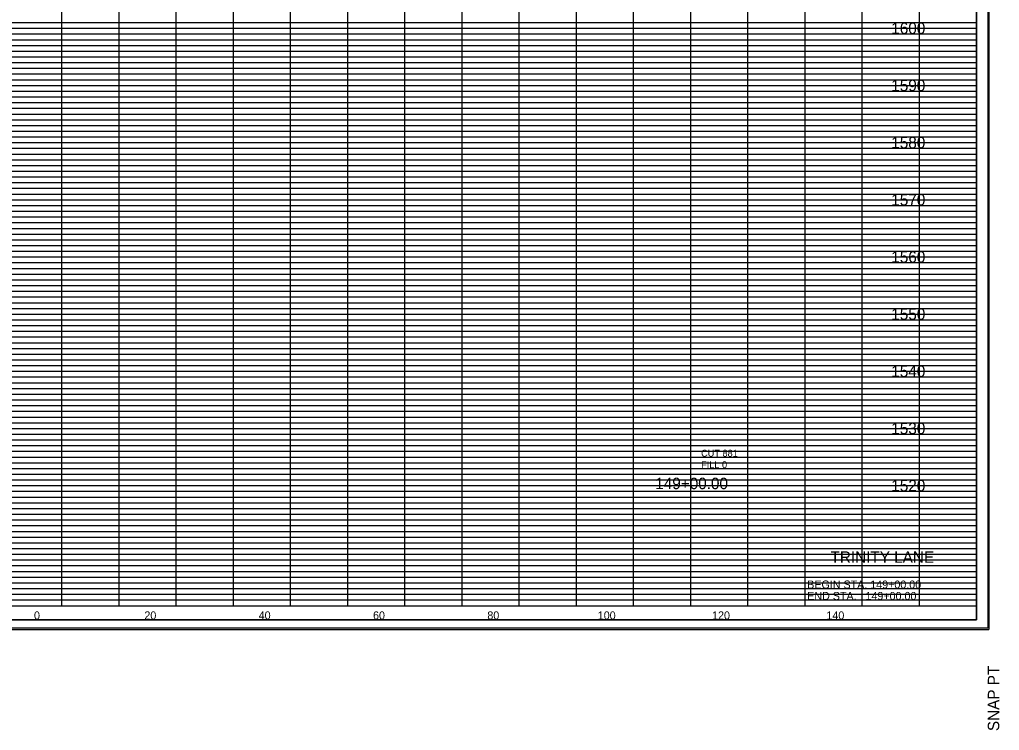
# Model space of a CAD drawing. Extents: x 980 to 1380, y 1248 to 3387.
# Drawn here: x 1152.6 to 1324, y 2868.2 to 2992.5 of the extents above; entities that cross this region are included whole.
import ezdxf

# ---------------------------------------------------------------- set-up
doc = ezdxf.new("R2010")
doc.units = 0
for name, color, linetype in [('DESIGN - SHEET - Corner Text', 7, 'Continuous'), ('DESIGN - SHEET - Light Grid', 7, 'Continuous'), ('DESIGN - SHEET - Linework', 7, 'Continuous'), ('DESIGN - SHEET - Plot Shape', 7, 'Continuous'), ('DESIGN - TYPICAL - Text', 7, 'Continuous')]:
    doc.layers.add(name, color=color, linetype=linetype)

# ---------------------------------------------------------------- blocks, each defined once
blk = doc.blocks.new('XSTSHT')
at = {"layer": 'DESIGN - SHEET - Light Grid'}
for p, q in [((8, 10.2), (16, 10.2)), ((16, 10.2), (24, 10.2)), ((24, 10.2), (32, 10.2)), ((8, 10.1), (16, 10.1)), ((16, 10.1), (24, 10.1)), ((24, 10.1), (32, 10.1)), ((8, 9.9), (16, 9.9)), ((8, 9.8), (16, 9.8)), ((16, 9.9), (24, 9.9)), ((16, 9.8), (24, 9.8)), ((24, 9.9), (32, 9.9)), ((24, 9.8), (32, 9.8)), ((8, 9.7), (16, 9.7)), ((8, 9.6), (16, 9.6)), ((16, 9.7), (24, 9.7)), ((16, 9.6), (24, 9.6)), ((24, 9.7), (32, 9.7)), ((24, 9.6), (32, 9.6)), ((8, 9.5), (16, 9.5)), ((16, 9.5), (24, 9.5)), ((24, 9.5), (32, 9.5)), ((8, 9.4), (16, 9.4)), ((8, 9.3), (16, 9.3)), ((16, 9.4), (24, 9.4)), ((16, 9.3), (24, 9.3)), ((24, 9.4), (32, 9.4)), ((24, 9.3), (32, 9.3)), ((8, 9.2), (16, 9.2)), ((8, 9.1), (16, 9.1)), ((16, 9.2), (24, 9.2)), ((16, 9.1), (24, 9.1)), ((24, 9.2), (32, 9.2)), ((24, 9.1), (32, 9.1)), ((8, 8.9), (16, 8.9)), ((8, 8.8), (16, 8.8)), ((16, 8.9), (24, 8.9)), ((16, 8.8), (24, 8.8)), ((24, 8.9), (32, 8.9)), ((24, 8.8), (32, 8.8)), ((8, 8.7), (16, 8.7)), ((8, 8.6), (16, 8.6)), ((16, 8.7), (24, 8.7)), ((16, 8.6), (24, 8.6)), ((24, 8.7), (32, 8.7)), ((24, 8.6), (32, 8.6)), ((8, 8.5), (16, 8.5)), ((8, 8.4), (16, 8.4)), ((16, 8.5), (24, 8.5)), ((16, 8.4), (24, 8.4)), ((24, 8.5), (32, 8.5)), ((24, 8.4), (32, 8.4)), ((8, 8.3), (16, 8.3)), ((16, 8.3), (24, 8.3)), ((24, 8.3), (32, 8.3)), ((8, 8.2), (16, 8.2)), ((8, 8.1), (16, 8.1)), ((16, 8.2), (24, 8.2)), ((16, 8.1), (24, 8.1)), ((24, 8.2), (32, 8.2)), ((24, 8.1), (32, 8.1)), ((8, 7.9), (16, 7.9)), ((16, 7.9), (24, 7.9)), ((24, 7.9), (32, 7.9)), ((8, 7.8), (16, 7.8)), ((16, 7.8), (24, 7.8)), ((24, 7.8), (32, 7.8)), ((8, 7.7), (16, 7.7)), ((8, 7.6), (16, 7.6)), ((16, 7.7), (24, 7.7)), ((16, 7.6), (24, 7.6)), ((24, 7.7), (32, 7.7)), ((24, 7.6), (32, 7.6)), ((8, 7.5), (16, 7.5)), ((8, 7.4), (16, 7.4)), ((16, 7.5), (24, 7.5)), ((16, 7.4), (24, 7.4)), ((24, 7.5), (32, 7.5)), ((24, 7.4), (32, 7.4)), ((8, 7.3), (16, 7.3)), ((8, 7.2), (16, 7.2)), ((16, 7.3), (24, 7.3)), ((16, 7.2), (24, 7.2)), ((24, 7.3), (32, 7.3)), ((24, 7.2), (32, 7.2)), ((8, 7.1), (16, 7.1)), ((16, 7.1), (24, 7.1)), ((24, 7.1), (32, 7.1)), ((8, 6.9), (16, 6.9)), ((16, 6.9), (24, 6.9)), ((24, 6.9), (32, 6.9)), ((8, 6.8), (16, 6.8)), ((8, 6.7), (16, 6.7)), ((16, 6.8), (24, 6.8)), ((16, 6.7), (24, 6.7)), ((24, 6.8), (32, 6.8)), ((24, 6.7), (32, 6.7)), ((8, 6.6), (16, 6.6)), ((16, 6.6), (24, 6.6)), ((24, 6.6), (32, 6.6)), ((8, 6.5), (16, 6.5)), ((8, 6.4), (16, 6.4)), ((16, 6.5), (24, 6.5)), ((16, 6.4), (24, 6.4)), ((24, 6.5), (32, 6.5)), ((24, 6.4), (32, 6.4)), ((8, 6.3), (16, 6.3)), ((8, 6.2), (16, 6.2)), ((16, 6.3), (24, 6.3)), ((16, 6.2), (24, 6.2)), ((24, 6.3), (32, 6.3)), ((24, 6.2), (32, 6.2)), ((8, 6.1), (16, 6.1)), ((16, 6.1), (24, 6.1)), ((24, 6.1), (32, 6.1)), ((8, 5.9), (16, 5.9)), ((16, 5.9), (24, 5.9)), ((24, 5.9), (32, 5.9)), ((8, 5.8), (16, 5.8)), ((8, 5.7), (16, 5.7)), ((16, 5.8), (24, 5.8)), ((16, 5.7), (24, 5.7)), ((24, 5.8), (32, 5.8)), ((24, 5.7), (32, 5.7)), ((8, 5.6), (16, 5.6)), ((8, 5.5), (16, 5.5)), ((16, 5.6), (24, 5.6)), ((16, 5.5), (24, 5.5)), ((24, 5.6), (32, 5.6)), ((24, 5.5), (32, 5.5)), ((8, 5.4), (16, 5.4)), ((16, 5.4), (24, 5.4)), ((24, 5.4), (32, 5.4)), ((8, 5.3), (16, 5.3)), ((8, 5.2), (16, 5.2)), ((16, 5.3), (24, 5.3)), ((16, 5.2), (24, 5.2)), ((24, 5.3), (32, 5.3)), ((24, 5.2), (32, 5.2)), ((8, 5.1), (16, 5.1)), ((16, 5.1), (24, 5.1)), ((24, 5.1), (32, 5.1)), ((8, 4.9), (16, 4.9)), ((8, 4.8), (16, 4.8)), ((16, 4.9), (24, 4.9)), ((16, 4.8), (24, 4.8)), ((24, 4.9), (32, 4.9)), ((24, 4.8), (32, 4.8)), ((8, 4.7), (16, 4.7)), ((16, 4.7), (24, 4.7)), ((24, 4.7), (32, 4.7)), ((8, 4.6), (16, 4.6)), ((8, 4.5), (16, 4.5)), ((16, 4.6), (24, 4.6)), ((16, 4.5), (24, 4.5)), ((24, 4.6), (32, 4.6)), ((24, 4.5), (32, 4.5)), ((8, 4.4), (16, 4.4)), ((8, 4.3), (16, 4.3)), ((16, 4.4), (24, 4.4)), ((16, 4.3), (24, 4.3)), ((24, 4.4), (32, 4.4)), ((24, 4.3), (32, 4.3)), ((8, 4.2), (16, 4.2)), ((16, 4.2), (24, 4.2)), ((24, 4.2), (32, 4.2)), ((8, 4.1), (16, 4.1)), ((16, 4.1), (24, 4.1)), ((24, 4.1), (32, 4.1)), ((8, 3.9), (16, 3.9)), ((8, 3.8), (16, 3.8)), ((16, 3.9), (24, 3.9)), ((16, 3.8), (24, 3.8)), ((24, 3.9), (32, 3.9)), ((24, 3.8), (32, 3.8)), ((8, 3.7), (16, 3.7)), ((8, 3.6), (16, 3.6)), ((16, 3.7), (24, 3.7)), ((16, 3.6), (24, 3.6)), ((24, 3.7), (32, 3.7)), ((24, 3.6), (32, 3.6)), ((8, 3.5), (16, 3.5)), ((16, 3.5), (24, 3.5)), ((24, 3.5), (32, 3.5)), ((8, 3.4), (16, 3.4)), ((8, 3.3), (16, 3.3)), ((16, 3.4), (24, 3.4)), ((16, 3.3), (24, 3.3)), ((24, 3.4), (32, 3.4)), ((24, 3.3), (32, 3.3)), ((8, 3.2), (16, 3.2)), ((8, 3.1), (16, 3.1)), ((16, 3.2), (24, 3.2)), ((16, 3.1), (24, 3.1)), ((24, 3.2), (32, 3.2)), ((24, 3.1), (32, 3.1)), ((8, 2.9), (16, 2.9)), ((8, 2.8), (16, 2.8)), ((16, 2.9), (24, 2.9)), ((16, 2.8), (24, 2.8)), ((24, 2.9), (32, 2.9)), ((24, 2.8), (32, 2.8)), ((8, 2.7), (16, 2.7)), ((8, 2.6), (16, 2.6)), ((16, 2.7), (24, 2.7)), ((16, 2.6), (24, 2.6)), ((24, 2.7), (32, 2.7)), ((24, 2.6), (32, 2.6)), ((8, 2.5), (16, 2.5)), ((8, 2.4), (16, 2.4)), ((16, 2.5), (24, 2.5)), ((16, 2.4), (24, 2.4)), ((24, 2.5), (32, 2.5)), ((24, 2.4), (32, 2.4)), ((8, 2.3), (16, 2.3)), ((16, 2.3), (24, 2.3)), ((24, 2.3), (32, 2.3)), ((8, 2.2), (16, 2.2)), ((8, 2.1), (16, 2.1)), ((16, 2.2), (24, 2.2)), ((16, 2.1), (24, 2.1)), ((24, 2.2), (32, 2.2)), ((24, 2.1), (32, 2.1)), ((8, 1.9), (16, 1.9)), ((16, 1.9), (24, 1.9)), ((24, 1.9), (32, 1.9)), ((8, 1.8), (16, 1.8)), ((16, 1.8), (24, 1.8)), ((24, 1.8), (32, 1.8)), ((8, 1.7), (16, 1.7)), ((8, 1.6), (16, 1.6)), ((16, 1.7), (24, 1.7)), ((16, 1.6), (24, 1.6)), ((24, 1.7), (32, 1.7)), ((24, 1.6), (32, 1.6)), ((8, 1.5), (16, 1.5)), ((8, 1.4), (16, 1.4)), ((16, 1.5), (24, 1.5)), ((16, 1.4), (24, 1.4)), ((24, 1.5), (32, 1.5)), ((24, 1.4), (32, 1.4)), ((8, 1.3), (16, 1.3)), ((8, 1.2), (16, 1.2)), ((16, 1.3), (24, 1.3)), ((16, 1.2), (24, 1.2)), ((24, 1.3), (32, 1.3)), ((24, 1.2), (32, 1.2)), ((8, 1.1), (16, 1.1)), ((16, 1.1), (24, 1.1)), ((24, 1.1), (32, 1.1)), ((8, 0.9), (16, 0.9)), ((16, 0.9), (24, 0.9)), ((24, 0.9), (32, 0.9)), ((8, 0.8), (16, 0.8)), ((8, 0.7), (16, 0.7)), ((16, 0.8), (24, 0.8)), ((16, 0.7), (24, 0.7)), ((24, 0.8), (32, 0.8)), ((24, 0.7), (32, 0.7)), ((8, 0.6), (16, 0.6)), ((16, 0.6), (24, 0.6)), ((24, 0.6), (32, 0.6)), ((8, 0.5), (16, 0.5)), ((8, 0.4), (16, 0.4)), ((16, 0.5), (24, 0.5)), ((16, 0.4), (24, 0.4)), ((24, 0.5), (32, 0.5)), ((24, 0.4), (32, 0.4)), ((8, 0.3), (16, 0.3)), ((8, 0.2), (16, 0.2)), ((16, 0.3), (24, 0.3)), ((16, 0.2), (24, 0.2)), ((24, 0.3), (32, 0.3)), ((24, 0.2), (32, 0.2)), ((8, 0.1), (16, 0.1)), ((16, 0.1), (24, 0.1)), ((24, 0.1), (32, 0.1))]:
    blk.add_line(p, q, dxfattribs=at)
at = {"layer": 'DESIGN - SHEET - Linework'}
for p, q in [((32.217, 21.414), (32.217, -0.414)), ((16, 0), (16, 21)), ((17, 0), (17, 21)), ((18, 0), (18, 21)), ((19, 0), (19, 21)), ((20, 0), (20, 21)), ((21, 0), (21, 21)), ((22, 0), (22, 21)), ((23, 0), (23, 21)), ((24, 0), (24, 21)), ((25, 0), (25, 21)), ((26, 0), (26, 21)), ((27, 0), (27, 21)), ((28, 0), (28, 20)), ((29, 0), (29, 20)), ((30, 0), (30, 20)), ((31, 0), (31, 20)), ((0, 10), (32, 10)), ((0, 9), (32, 9)), ((0, 8), (32, 8)), ((0, 7), (32, 7)), ((0, 6), (32, 6)), ((0, 5), (32, 5)), ((0, 4), (32, 4)), ((0, 3), (32, 3)), ((0, 2), (32, 2)), ((0, 1), (32, 1)), ((-1.823, -0.414), (32.217, -0.414))]:
    blk.add_line(p, q, dxfattribs=at)
blk.add_lwpolyline([(0, 21), (0, 0), (32, 0), (32, 21), (0, 21)], dxfattribs=at)
at = {"layer": 'DESIGN - SHEET - Plot Shape'}
for points in [[(-1.803, 21.394), (32.197, 21.394), (32.197, -0.394), (-1.803, -0.394)], [(-0.85, 21), (32, 21), (32, -0.25), (-0.85, -0.25)]]:
    blk.add_lwpolyline(points, close=True, dxfattribs=at)
at = {"layer": 'DESIGN - SHEET - Corner Text'}
blk.add_text('SNAP PT  ', height=0.2, rotation=90, dxfattribs=at).set_placement((32.397, -2.194))

msp = doc.modelspace()

# ---------------------------------------------------------------- linework, layer by layer
at = {"layer": 'DESIGN - SHEET - Plot Shape'}
msp.add_lwpolyline([(991.5, 2887.5), (1320, 2887.5), (1320, 3100), (991.5, 3100)], close=True, dxfattribs=at)

# ---------------------------------------------------------------- block references
at = {"layer": 'DESIGN - TYPICAL - Text', "xscale": 10, "yscale": 10}
msp.add_blockref('XSTSHT', (1000, 2890), dxfattribs=at)

# ---------------------------------------------------------------- texts
at = {"layer": 'DESIGN - SHEET - Corner Text'}
for s, height, p in [('TRINITY LANE', 2, (1294.45, 2897.5)), ('BEGIN STA. 149+00.00', 1.4, (1290.38, 2893)), ('END STA.   149+00.00', 1.4, (1290.38, 2891))]:
    msp.add_text(s, height=height, dxfattribs=at).set_placement(p)
at = {"layer": 'DESIGN - TYPICAL - Text'}
for s, height, p in [('     1600     ', 2, (1301.37, 2990)), ('     1590     ', 2, (1301.37, 2980)), ('     1580     ', 2, (1301.37, 2970)), ('     1570     ', 2, (1301.37, 2960)), ('     1560     ', 2, (1301.37, 2950)), ('     1550     ', 2, (1301.37, 2940)), ('     1540     ', 2, (1301.37, 2930)), ('     1530     ', 2, (1301.37, 2920)), ('CUT 881', 1.2, (1271.81, 2916.07)), ('FILL 0', 1.2, (1271.81, 2914.07)), ('     149+00.00     ', 2, (1260.08, 2910.38)), ('     1520     ', 2, (1301.37, 2910)), ('     0     ', 1.4, (1152.51, 2887.6)), ('     0     ', 1.4, (1152.51, 2887.6)), ('     20     ', 1.4, (1171.82, 2887.6)), ('     40     ', 1.4, (1191.82, 2887.6)), ('     60     ', 1.4, (1211.82, 2887.6)), ('     80     ', 1.4, (1231.82, 2887.6)), ('     100     ', 1.4, (1251.14, 2887.6)), ('     120     ', 1.4, (1271.14, 2887.6)), ('     140     ', 1.4, (1291.14, 2887.6))]:
    msp.add_text(s, height=height, dxfattribs=at).set_placement(p)

doc.saveas('drawing.dxf')
